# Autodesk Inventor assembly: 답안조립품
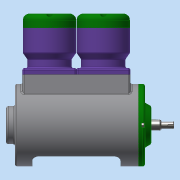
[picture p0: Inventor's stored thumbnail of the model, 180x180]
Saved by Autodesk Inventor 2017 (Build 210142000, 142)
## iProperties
Part Number: 답안조립품
Material: 일반
Document SubType Name: Assembly
Designer: Administrator
Mass: 7371.37 g
Surface Area: 5215.2 cm^2
Volume: 2062.19 cm^3
Density: 3.57453 g/cm^3
Author: Administrator
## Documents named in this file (16)
- C:\Users\Administrator\Desktop\620106V1005\답안조립품.iam
- C:\Users\Administrator\Desktop\620106V1005\너트 M4.ipt
- C:\Users\Administrator\Desktop\620106V1005\베어링 6303.ipt
- C:\Users\Administrator\Desktop\620106V1005\본체.ipt
- C:\Users\Administrator\Desktop\620106V1005\볼트 M4 x 12.ipt
- C:\Users\Administrator\Desktop\620106V1005\볼트 M5 x 20.ipt
- C:\Users\Administrator\Desktop\620106V1005\실린더.ipt
- C:\Users\Administrator\Desktop\620106V1005\실린더헤드.ipt
- C:\Users\Administrator\Desktop\620106V1005\앞커버.ipt
- C:\Users\Administrator\Desktop\620106V1005\오일 실 17 x 32 x 8.ipt
- C:\Users\Administrator\Desktop\620106V1005\육각 머리 볼트 M4 x 16.ipt
- C:\Users\Administrator\Desktop\620106V1005\커넥팅로드 엔드.ipt
- C:\Users\Administrator\Desktop\620106V1005\커넥팅로드.ipt
- C:\Users\Administrator\Desktop\620106V1005\크랭크축.ipt
- C:\Users\Administrator\Desktop\620106V1005\피스톤.ipt
- C:\Users\Administrator\Desktop\620106V1005\피스톤핀.ipt
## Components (4 placed, 2 different names)
1. 피스톤:1
2. 피스톤핀:1
3. 피스톤:2
4. 피스톤핀:2
